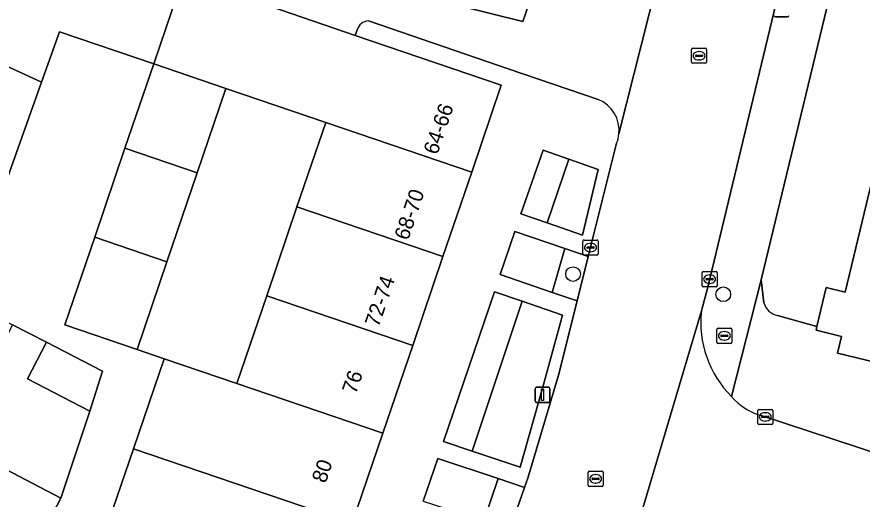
# Model space of a CAD drawing. Extents: x 162803 to 163818, y 381639 to 382475.
# Drawn here: x 163112.3 to 163168.5, y 382038.7 to 382070.7 of the extents above; entities that cross this region are included whole.
import ezdxf

# ---------------------------------------------------------------- set-up
doc = ezdxf.new("R2010")
doc.units = 0
for name, color, linetype in [('IMGEO_Boom', 7, 'Continuous'), ('IMGEO_Brandkraan', 7, 'Continuous'), ('IMGEO_Erf', 7, 'Continuous'), ('IMGEO_Groenvoorziening', 7, 'Continuous'), ('IMGEO_Kolk', 7, 'Continuous'), ('IMGEO_Lichtmast', 7, 'Continuous'), ('IMGEO_Muur', 7, 'Continuous'), ('IMGEO_Pand', 7, 'Continuous'), ('IMGEO_Pand_nummerreeks', 7, 'Continuous'), ('IMGEO_Rijbaan_lokaal_open', 7, 'Continuous'), ('IMGEO_Rioolput', 7, 'Continuous'), ('IMGEO_Voetpad_open', 7, 'Continuous')]:
    doc.layers.add(name, color=color, linetype=linetype)

msp = doc.modelspace()

# ---------------------------------------------------------------- linework, layer by layer
at = {"layer": 'IMGEO_Boom'}
for centre in [(163149.234, 382053.653), (163159.221, 382052.313)]:
    msp.add_circle(centre, 0.489, dxfattribs=at)
at = {"layer": 'IMGEO_Brandkraan'}
for p, q in [((163158.796, 382049.126), (163158.796, 382049.978)), ((163158.871, 382050.052), (163159.723, 382050.052)), ((163159.797, 382049.978), (163159.797, 382049.126)), ((163159.055, 382049.546), (163159.055, 382049.558)), ((163159.493, 382049.509), (163159.095, 382049.509)), ((163159.098, 382049.595), (163159.496, 382049.595)), ((163159.307, 382049.272), (163159.282, 382049.272)), ((163159.284, 382049.832), (163159.309, 382049.832)), ((163159.539, 382049.558), (163159.539, 382049.546)), ((163159.723, 382049.052), (163158.871, 382049.052))]:
    msp.add_line(p, q, dxfattribs=at)
for points in [[(163158.796, 382049.126), (163158.796, 382049.978)], [(163158.871, 382050.052), (163159.723, 382050.052)], [(163159.797, 382049.978), (163159.797, 382049.126)], [(163159.723, 382049.052), (163158.871, 382049.052)]]:
    msp.add_lwpolyline(points, dxfattribs=at)
for centre, radius, start, end in [((163158.873, 382049.976), 0.0765, 91.552, 178.448), ((163158.873, 382049.976), 0.0765, 91.552, 178.448), ((163159.721, 382049.976), 0.0765, 1.552, 88.448), ((163159.721, 382049.976), 0.0765, 1.552, 88.448), ((163159.095, 382049.555), 0.0403, 85.8775, 175.7526), ((163159.092, 382049.545), 0.0366, 178.938, 274.7102), ((163159.496, 382049.552), 0.043, 264.8664, 352.4533), ((163159.5, 382049.557), 0.0386, 1.7309, 96.639), ((163158.873, 382049.128), 0.0765, 181.552, 268.448), ((163158.873, 382049.128), 0.0765, 181.552, 268.448), ((163159.721, 382049.128), 0.0765, 271.552, 358.448), ((163159.721, 382049.128), 0.0765, 271.552, 358.448)]:
    msp.add_arc(centre, radius, start, end, dxfattribs=at)
for centre, major_axis, ratio, start_param, end_param in [((163159.283, 382049.552), (-0.387, 0.002), 0.722429, 4.712389, 7.853982), ((163159.308, 382049.552), (-0.39, 0.002), 0.717154, 1.570796, 4.712389)]:
    msp.add_ellipse(centre, major_axis=major_axis, ratio=ratio, start_param=start_param, end_param=end_param, dxfattribs=at)
at = {"layer": 'IMGEO_Erf'}
for points in [[(163172.549, 382098.026), (163172.362, 382097.253), (163161.731, 382053.278), (163161.928, 382051.741)], [(163162.82, 382050.904), (163165.45, 382050.178), (163166.071, 382052.76), (163167.324, 382052.459), (163177.779, 382095.946)], [(163082.461, 382055.81), (163087.892, 382052.981), (163093.324, 382050.152), (163098.755, 382047.324), (163100.033, 382049.778), (163105.464, 382046.948), (163104.187, 382044.495), (163109.618, 382041.666), (163115.183, 382038.768), (163117.107, 382044.537), (163112.953, 382046.7), (163114.222, 382049.137), (163111.971, 382050.272), (163110.711, 382047.851), (163107.035, 382049.765), (163108.296, 382052.186), (163108.755, 382051.947), (163109.589, 382054.37), (163089.408, 382064.775), (163064.435, 382077.65)]]:
    msp.add_lwpolyline(points, dxfattribs=at)
msp.add_lwpolyline([(163120.246, 382048.641), (163122.041, 382048.03), (163126.886, 382046.382), (163128.871, 382052.216), (163130.88, 382058.123), (163132.79, 382063.739), (163126.151, 382065.997), (163124.24, 382060.382), (163122.231, 382054.475)], close=True, dxfattribs=at)
msp.add_arc((163163.069, 382052.063), 1.186, 195.7778, 257.8662, dxfattribs=at)
at = {"layer": 'IMGEO_Groenvoorziening'}
for points in [[(163148.958, 382061.287), (163147.249, 382061.887), (163145.757, 382057.661), (163147.518, 382057.053)], [(163150.897, 382060.606), (163148.958, 382061.287), (163147.518, 382057.053), (163149.854, 382056.246)], [(163148.682, 382055.35), (163145.352, 382056.482), (163144.387, 382053.618), (163147.842, 382052.44)], [(163150.238, 382054.821), (163148.682, 382055.35), (163147.842, 382052.44), (163149.499, 382051.875)], [(163145.844, 382051.847), (163144.002, 382052.474), (163140.62, 382042.534), (163142.537, 382041.891)], [(163148.531, 382050.933), (163145.844, 382051.847), (163142.537, 382041.891), (163145.717, 382040.826), (163147.248, 382046.227)], [(163144.249, 382040.06), (163140.233, 382041.398), (163139.267, 382038.558), (163143.297, 382037.246)], [(163146.012, 382039.473), (163144.249, 382040.06), (163143.297, 382037.246), (163145.033, 382036.681)]]:
    msp.add_lwpolyline(points, close=True, dxfattribs=at)
at = {"layer": 'IMGEO_Kolk'}
for p, q in [((163149.893, 382054.994), (163149.893, 382055.846)), ((163149.968, 382055.92), (163150.82, 382055.92)), ((163150.195, 382055.463), (163150.593, 382055.463)), ((163150.381, 382055.7), (163150.406, 382055.7)), ((163150.894, 382055.846), (163150.894, 382054.994)), ((163150.82, 382054.92), (163149.968, 382054.92)), ((163150.152, 382055.414), (163150.152, 382055.426)), ((163150.59, 382055.377), (163150.192, 382055.377)), ((163150.404, 382055.14), (163150.379, 382055.14)), ((163150.636, 382055.426), (163150.636, 382055.414)), ((163157.887, 382053.817), (163158.739, 382053.817)), ((163157.812, 382052.891), (163157.812, 382053.743)), ((163158.071, 382053.311), (163158.071, 382053.323)), ((163158.509, 382053.274), (163158.111, 382053.274)), ((163158.114, 382053.36), (163158.512, 382053.36)), ((163158.3, 382053.597), (163158.325, 382053.597)), ((163158.555, 382053.323), (163158.555, 382053.311)), ((163158.813, 382053.743), (163158.813, 382052.891)), ((163158.739, 382052.817), (163157.887, 382052.817)), ((163158.323, 382053.037), (163158.298, 382053.037)), ((163161.513, 382043.736), (163161.513, 382044.588)), ((163161.588, 382044.662), (163162.44, 382044.662)), ((163162.001, 382044.442), (163162.026, 382044.442)), ((163162.514, 382044.588), (163162.514, 382043.736)), ((163162.44, 382043.662), (163161.588, 382043.662)), ((163161.772, 382044.156), (163161.772, 382044.168)), ((163162.21, 382044.119), (163161.812, 382044.119)), ((163161.815, 382044.205), (163162.213, 382044.205)), ((163162.024, 382043.882), (163161.999, 382043.882)), ((163162.256, 382044.168), (163162.256, 382044.156))]:
    msp.add_line(p, q, dxfattribs=at)
for points in [[(163149.893, 382054.994), (163149.893, 382055.846)], [(163149.968, 382055.92), (163150.82, 382055.92)], [(163150.894, 382055.846), (163150.894, 382054.994)], [(163150.82, 382054.92), (163149.968, 382054.92)], [(163157.887, 382053.817), (163158.739, 382053.817)], [(163157.812, 382052.891), (163157.812, 382053.743)], [(163158.813, 382053.743), (163158.813, 382052.891)], [(163158.739, 382052.817), (163157.887, 382052.817)], [(163161.513, 382043.736), (163161.513, 382044.588)], [(163161.588, 382044.662), (163162.44, 382044.662)], [(163162.514, 382044.588), (163162.514, 382043.736)], [(163162.44, 382043.662), (163161.588, 382043.662)]]:
    msp.add_lwpolyline(points, dxfattribs=at)
for centre, radius, start, end in [((163149.97, 382055.844), 0.0765, 91.552, 178.448), ((163149.97, 382055.844), 0.0765, 91.552, 178.448), ((163150.192, 382055.423), 0.0403, 85.8775, 175.7526), ((163150.597, 382055.425), 0.0386, 1.7309, 96.639), ((163150.818, 382055.844), 0.0765, 1.552, 88.448), ((163150.818, 382055.844), 0.0765, 1.552, 88.448), ((163149.97, 382054.996), 0.0765, 181.552, 268.448), ((163149.97, 382054.996), 0.0765, 181.552, 268.448), ((163150.189, 382055.413), 0.0366, 178.938, 274.7102), ((163150.593, 382055.42), 0.043, 264.8664, 352.4533), ((163150.818, 382054.996), 0.0765, 271.552, 358.448), ((163150.818, 382054.996), 0.0765, 271.552, 358.448), ((163157.889, 382053.741), 0.0765, 91.552, 178.448), ((163157.889, 382053.741), 0.0765, 91.552, 178.448), ((163158.737, 382053.741), 0.0765, 1.552, 88.448), ((163158.737, 382053.741), 0.0765, 1.552, 88.448), ((163158.111, 382053.32), 0.0403, 85.8775, 175.7526), ((163158.108, 382053.31), 0.0366, 178.938, 274.7102), ((163158.512, 382053.317), 0.043, 264.8664, 352.4533), ((163158.516, 382053.322), 0.0386, 1.7309, 96.639), ((163157.889, 382052.893), 0.0765, 181.552, 268.448), ((163157.889, 382052.893), 0.0765, 181.552, 268.448), ((163158.737, 382052.893), 0.0765, 271.552, 358.448), ((163158.737, 382052.893), 0.0765, 271.552, 358.448), ((163161.59, 382044.586), 0.0765, 91.552, 178.448), ((163161.59, 382044.586), 0.0765, 91.552, 178.448), ((163162.438, 382044.586), 0.0765, 1.552, 88.448), ((163162.438, 382044.586), 0.0765, 1.552, 88.448), ((163161.59, 382043.738), 0.0765, 181.552, 268.448), ((163161.59, 382043.738), 0.0765, 181.552, 268.448), ((163161.812, 382044.165), 0.0403, 85.8775, 175.7526), ((163161.809, 382044.155), 0.0366, 178.938, 274.7102), ((163162.213, 382044.162), 0.043, 264.8664, 352.4533), ((163162.217, 382044.167), 0.0386, 1.7309, 96.639), ((163162.438, 382043.738), 0.0765, 271.552, 358.448), ((163162.438, 382043.738), 0.0765, 271.552, 358.448)]:
    msp.add_arc(centre, radius, start, end, dxfattribs=at)
for centre, major_axis, ratio, start_param, end_param in [((163150.38, 382055.42), (-0.387, 0.002), 0.722429, 4.712389, 7.853982), ((163150.405, 382055.42), (-0.39, 0.002), 0.717154, 1.570796, 4.712389), ((163158.299, 382053.317), (-0.387, 0.002), 0.722429, 4.712389, 7.853982), ((163158.324, 382053.317), (-0.39, 0.002), 0.717154, 1.570796, 4.712389), ((163162, 382044.162), (-0.387, 0.002), 0.722429, 4.712389, 7.853982), ((163162.025, 382044.162), (-0.39, 0.002), 0.717154, 1.570796, 4.712389)]:
    msp.add_ellipse(centre, major_axis=major_axis, ratio=ratio, start_param=start_param, end_param=end_param, dxfattribs=at)
at = {"layer": 'IMGEO_Lichtmast'}
for p, q in [((163163.49, 382070.746), (163162.7, 382070.746)), ((163162.7, 382070.746), (163163.49, 382070.746)), ((163146.708, 382045.23), (163146.708, 382046.03)), ((163146.708, 382046.03), (163146.708, 382045.23)), ((163146.808, 382046.13), (163147.598, 382046.13)), ((163147.598, 382046.13), (163146.808, 382046.13)), ((163147.698, 382046.03), (163147.698, 382045.23)), ((163147.698, 382045.23), (163147.698, 382046.03)), ((163147.598, 382045.13), (163146.808, 382045.13)), ((163146.808, 382045.13), (163147.598, 382045.13))]:
    msp.add_line(p, q, dxfattribs=at)
msp.add_lwpolyline([(163147.128, 382046.005), (163147.278, 382046.005), (163147.278, 382045.255), (163147.128, 382045.255), (163147.128, 382046.005)], dxfattribs=at)
for centre, start, end in [((163162.7, 382070.846), 180, 270), ((163162.7, 382070.846), 180, 270), ((163163.49, 382070.846), 270, 0), ((163163.49, 382070.846), 270, 0), ((163146.808, 382046.03), 90, 180), ((163146.808, 382046.03), 90, 180), ((163147.598, 382046.03), 0, 90), ((163147.598, 382046.03), 360, 90), ((163146.808, 382045.23), 180, 270), ((163146.808, 382045.23), 180, 270), ((163147.598, 382045.23), 270, 0), ((163147.598, 382045.23), 270, 0)]:
    msp.add_arc(centre, 0.1, start, end, dxfattribs=at)
at = {"layer": 'IMGEO_Muur'}
for points in [[(163161.731, 382053.278), (163172.362, 382097.253)], [(163161.928, 382051.741), (163161.731, 382053.278)], [(163165.45, 382050.178), (163162.82, 382050.904)]]:
    msp.add_lwpolyline(points, dxfattribs=at)
msp.add_arc((163163.069, 382052.063), 1.186, 195.7778, 257.8662, dxfattribs=at)
at = {"layer": 'IMGEO_Pand'}
for points in [[(163177.644, 382098.685), (163177.029, 382096.127), (163177.779, 382095.946), (163167.324, 382052.459), (163166.071, 382052.76), (163165.45, 382050.178), (163165.388, 382049.919), (163167.09, 382049.51), (163166.822, 382048.392), (163171.412, 382047.289), (163171.798, 382048.894), (163175.197, 382048.077), (163186.218, 382093.918), (163183.399, 382094.595), (163183.96, 382096.93)], [(163094.344, 382075.452), (163089.408, 382064.775), (163109.589, 382054.37), (163113.901, 382066.416)], [(163142.496, 382060.438), (163144.457, 382066.204), (163134.752, 382069.505), (163123.339, 382073.465), (163121.353, 382067.628), (163126.151, 382065.997), (163132.79, 382063.739)], [(163124.24, 382060.382), (163126.151, 382065.997), (163121.353, 382067.628), (163119.444, 382062.013)], [(163130.88, 382058.123), (163140.585, 382054.822), (163142.496, 382060.438), (163132.79, 382063.739)], [(163117.434, 382056.106), (163122.231, 382054.475), (163124.24, 382060.382), (163119.444, 382062.013)], [(163130.88, 382058.123), (163128.871, 382052.216), (163138.576, 382048.915), (163140.585, 382054.822)], [(163117.434, 382056.106), (163115.449, 382050.273), (163120.246, 382048.641), (163122.231, 382054.475)], [(163136.589, 382043.077), (163138.576, 382048.915), (163128.871, 382052.216), (163126.886, 382046.382)], [(163114.222, 382049.137), (163112.953, 382046.7), (163117.107, 382044.537), (163117.955, 382047.193)], [(163120.005, 382042.044), (163134.554, 382037.095), (163136.589, 382043.077), (163126.886, 382046.382), (163122.041, 382048.03)], [(163120.005, 382042.044), (163118.089, 382036.41), (163132.638, 382031.462), (163134.554, 382037.095)], [(163106.058, 382034.831), (163111.619, 382031.924), (163115.183, 382038.768), (163109.618, 382041.666)]]:
    msp.add_lwpolyline(points, close=True, dxfattribs=at)
at = {"layer": 'IMGEO_Rijbaan_lokaal_open'}
for points in [[(163134.859, 382115.115), (163136.272, 382121.013), (163137.778, 382127.293), (163139.19, 382133.185), (163132.413, 382134.805), (163129.559, 382123.281), (163129.714, 382123.244), (163130.175, 382123.133), (163120.073, 382080.932), (163119.585, 382081.072), (163118.665, 382077.202), (163145.899, 382070.444), (163146.816, 382073.136), (163138.433, 382075.277)], [(163030.56, 382064.019), (163032.699, 382067.446), (163033.931, 382069.45), (163035.364, 382071.783), (163038.869, 382078.512), (163042.26, 382083.224), (163044.389, 382086.312), (163045.258, 382087.591), (163055.907, 382084.983), (163056.76, 382088.134), (163066.455, 382085.51), (163081.226, 382081.513), (163094.344, 382075.452), (163113.901, 382066.416), (163115.096, 382069.756), (163121.353, 382067.628), (163123.339, 382073.465), (163134.752, 382069.505), (163134.887, 382069.879)], [(163152.479, 382071.728), (163147.417, 382072.983), (163146.816, 382073.136), (163145.899, 382070.444), (163118.665, 382077.202), (163119.585, 382081.072), (163101.444, 382085.414)], [(163157.77, 382051.207), (163158.197, 382052.792), (163165.19, 382081.932), (163157.326, 382083.853), (163154.833, 382073.132), (163154.796, 382072.986), (163152.284, 382062.975)], [(163152.284, 382062.975), (163154.796, 382072.986), (163154.833, 382073.132)], [(163135.629, 382070.476), (163144.923, 382067.304), (163150.913, 382065.26)], [(163152.125, 382062.345), (163150.238, 382054.821), (163149.499, 382051.875), (163148.26, 382046.936), (163146.227, 382040.085), (163146.012, 382039.473), (163145.033, 382036.681), (163143.1, 382031.171), (163141.728, 382027.565), (163140.726, 382024.934), (163139.78, 382022.212), (163139.729, 382022.089), (163138.836, 382019.935)], [(163139.46, 382016.281), (163138.285, 382013.516), (163143.832, 382011.14), (163146.235, 382017.05), (163147.599, 382020.265), (163148.28, 382022.097), (163149.261, 382024.736), (163152.342, 382033.275), (163152.905, 382034.812), (163157.77, 382051.207)], [(163157.77, 382051.207), (163152.905, 382034.812)], [(163159.5, 382037.762), (163159.567, 382037.737), (163160.645, 382037.327), (163176.484, 382032.15), (163186.097, 382029.003), (163194.957, 382026.049), (163197.135, 382032.623), (163161.734, 382044.254)]]:
    msp.add_lwpolyline(points, dxfattribs=at)
msp.add_lwpolyline([(163117.107, 382044.537), (163115.183, 382038.768), (163111.619, 382031.924), (163116.095, 382030.549), (163118.089, 382036.41), (163120.005, 382042.044), (163122.041, 382048.03), (163120.246, 382048.641), (163115.449, 382050.273), (163117.434, 382056.106), (163119.444, 382062.013), (163121.353, 382067.628), (163115.096, 382069.756), (163113.901, 382066.416), (163109.589, 382054.37), (163108.755, 382051.947), (163111.971, 382050.272), (163114.222, 382049.137), (163117.955, 382047.193)], close=True, dxfattribs=at)
for centre, radius, start, end in [((163135.66, 382069.678), 0.799, 92.2146, 165.4245), ((163150.065, 382063.197), 2.23, 354.2799, 67.6476), ((163150.018, 382063.212), 2.278, 337.6366, 354.0343), ((163164.651, 382050.43), 6.925, 173.5579, 225.1693), ((163162.87, 382048.177), 4.084, 220.6025, 253.8534)]:
    msp.add_arc(centre, radius, start, end, dxfattribs=at)
at = {"layer": 'IMGEO_Rioolput'}
for p, q in [((163157.114, 382067.738), (163157.114, 382068.59)), ((163157.189, 382068.664), (163158.041, 382068.664)), ((163157.602, 382068.444), (163157.627, 382068.444)), ((163158.115, 382068.59), (163158.115, 382067.738)), ((163157.373, 382068.158), (163157.373, 382068.17)), ((163157.811, 382068.121), (163157.413, 382068.121)), ((163157.416, 382068.207), (163157.814, 382068.207)), ((163157.625, 382067.884), (163157.6, 382067.884)), ((163157.857, 382068.17), (163157.857, 382068.158)), ((163158.041, 382067.664), (163157.189, 382067.664)), ((163150.233, 382039.622), (163150.233, 382040.474)), ((163150.308, 382040.548), (163151.16, 382040.548)), ((163150.721, 382040.328), (163150.746, 382040.328)), ((163151.234, 382040.474), (163151.234, 382039.622)), ((163150.492, 382040.042), (163150.492, 382040.054)), ((163150.93, 382040.005), (163150.532, 382040.005)), ((163150.535, 382040.091), (163150.933, 382040.091)), ((163150.744, 382039.768), (163150.719, 382039.768)), ((163150.976, 382040.054), (163150.976, 382040.042)), ((163151.16, 382039.548), (163150.308, 382039.548))]:
    msp.add_line(p, q, dxfattribs=at)
for points in [[(163157.114, 382067.738), (163157.114, 382068.59)], [(163157.189, 382068.664), (163158.041, 382068.664)], [(163158.115, 382068.59), (163158.115, 382067.738)], [(163158.041, 382067.664), (163157.189, 382067.664)], [(163150.233, 382039.622), (163150.233, 382040.474)], [(163150.308, 382040.548), (163151.16, 382040.548)], [(163151.234, 382040.474), (163151.234, 382039.622)], [(163151.16, 382039.548), (163150.308, 382039.548)]]:
    msp.add_lwpolyline(points, dxfattribs=at)
for centre, radius, start, end in [((163157.191, 382068.588), 0.0765, 91.552, 178.448), ((163157.191, 382068.588), 0.0765, 91.552, 178.448), ((163158.039, 382068.588), 0.0765, 1.552, 88.448), ((163158.039, 382068.588), 0.0765, 1.552, 88.448), ((163157.413, 382068.167), 0.0403, 85.8775, 175.7526), ((163157.41, 382068.157), 0.0366, 178.938, 274.7102), ((163157.814, 382068.164), 0.043, 264.8664, 352.4533), ((163157.818, 382068.169), 0.0386, 1.7309, 96.639), ((163157.191, 382067.74), 0.0765, 181.552, 268.448), ((163157.191, 382067.74), 0.0765, 181.552, 268.448), ((163158.039, 382067.74), 0.0765, 271.552, 358.448), ((163158.039, 382067.74), 0.0765, 271.552, 358.448), ((163150.31, 382040.472), 0.0765, 91.552, 178.448), ((163150.31, 382040.472), 0.0765, 91.552, 178.448), ((163151.158, 382040.472), 0.0765, 1.552, 88.448), ((163151.158, 382040.472), 0.0765, 1.552, 88.448), ((163150.532, 382040.051), 0.0403, 85.8775, 175.7526), ((163150.529, 382040.041), 0.0366, 178.938, 274.7102), ((163150.933, 382040.048), 0.043, 264.8664, 352.4533), ((163150.937, 382040.053), 0.0386, 1.7309, 96.639), ((163150.31, 382039.624), 0.0765, 181.552, 268.448), ((163150.31, 382039.624), 0.0765, 181.552, 268.448), ((163151.158, 382039.624), 0.0765, 271.552, 358.448), ((163151.158, 382039.624), 0.0765, 271.552, 358.448)]:
    msp.add_arc(centre, radius, start, end, dxfattribs=at)
for centre, major_axis, ratio, start_param, end_param in [((163157.601, 382068.164), (-0.387, 0.002), 0.722429, 4.712389, 7.853982), ((163157.626, 382068.164), (-0.39, 0.002), 0.717154, 1.570796, 4.712389), ((163150.72, 382040.048), (-0.387, 0.002), 0.722429, 4.712389, 7.853982), ((163150.745, 382040.048), (-0.39, 0.002), 0.717154, 1.570796, 4.712389)]:
    msp.add_ellipse(centre, major_axis=major_axis, ratio=ratio, start_param=start_param, end_param=end_param, dxfattribs=at)
at = {"layer": 'IMGEO_Voetpad_open'}
for points in [[(163169.308, 382099.118), (163165.855, 382084.706), (163165.19, 382081.932), (163158.197, 382052.792), (163157.77, 382051.207)], [(163159.769, 382045.519), (163161.731, 382053.278), (163172.362, 382097.253)], [(163150.913, 382065.26), (163144.923, 382067.304), (163135.629, 382070.476)], [(163134.887, 382069.879), (163134.752, 382069.505), (163144.457, 382066.204), (163142.496, 382060.438), (163140.585, 382054.822), (163138.576, 382048.915), (163136.589, 382043.077), (163134.554, 382037.095), (163132.638, 382031.462), (163130.644, 382025.6), (163116.683, 382030.349), (163114.074, 382025.081), (163112.302, 382021.503), (163113.017, 382021.144), (163123.144, 382015.469), (163123.601, 382014.833), (163124.04, 382013.268)], [(163139.267, 382038.558), (163140.233, 382041.398), (163144.249, 382040.06), (163146.012, 382039.473), (163146.227, 382040.085), (163148.26, 382046.936), (163149.499, 382051.875), (163147.842, 382052.44), (163144.387, 382053.618), (163145.352, 382056.482), (163148.682, 382055.35), (163150.238, 382054.821), (163152.125, 382062.345)], [(163161.928, 382051.741), (163161.731, 382053.278), (163159.769, 382045.519)], [(163171.412, 382047.289), (163166.822, 382048.392), (163167.09, 382049.51), (163165.388, 382049.919), (163165.45, 382050.178), (163162.82, 382050.904)], [(163161.734, 382044.254), (163197.135, 382032.623)]]:
    msp.add_lwpolyline(points, dxfattribs=at)
for points in [[(163147.518, 382057.053), (163145.757, 382057.661), (163147.249, 382061.887), (163148.958, 382061.287), (163150.897, 382060.606), (163149.854, 382056.246)], [(163144.002, 382052.474), (163145.844, 382051.847), (163148.531, 382050.933), (163147.248, 382046.227), (163145.717, 382040.826), (163142.537, 382041.891), (163140.62, 382042.534)]]:
    msp.add_lwpolyline(points, close=True, dxfattribs=at)
for centre, radius, start, end in [((163135.66, 382069.678), 0.799, 92.2146, 165.4245), ((163150.065, 382063.197), 2.23, 354.2799, 67.6476), ((163150.018, 382063.212), 2.278, 337.6366, 354.0343), ((163163.069, 382052.063), 1.186, 195.7778, 257.8662), ((163164.651, 382050.43), 6.925, 173.5579, 225.1693), ((163162.87, 382048.177), 4.084, 220.6025, 253.8534)]:
    msp.add_arc(centre, radius, start, end, dxfattribs=at)

# ---------------------------------------------------------------- texts
at = {"layer": 'IMGEO_Pand_nummerreeks'}
for s, rotation, p in [('64-66', 71.1872, (163140.204, 382061.535)), ('68-70', 71.2168, (163138.269, 382055.846)), ('72-74', 71.2166, (163136.309, 382050.081)), ('76', 71.2214, (163134.795, 382045.63)), ('80', 71.2151, (163132.782, 382039.711))]:
    msp.add_text(s, height=1, rotation=rotation, dxfattribs=at).set_placement(p)

doc.saveas('drawing.dxf')
